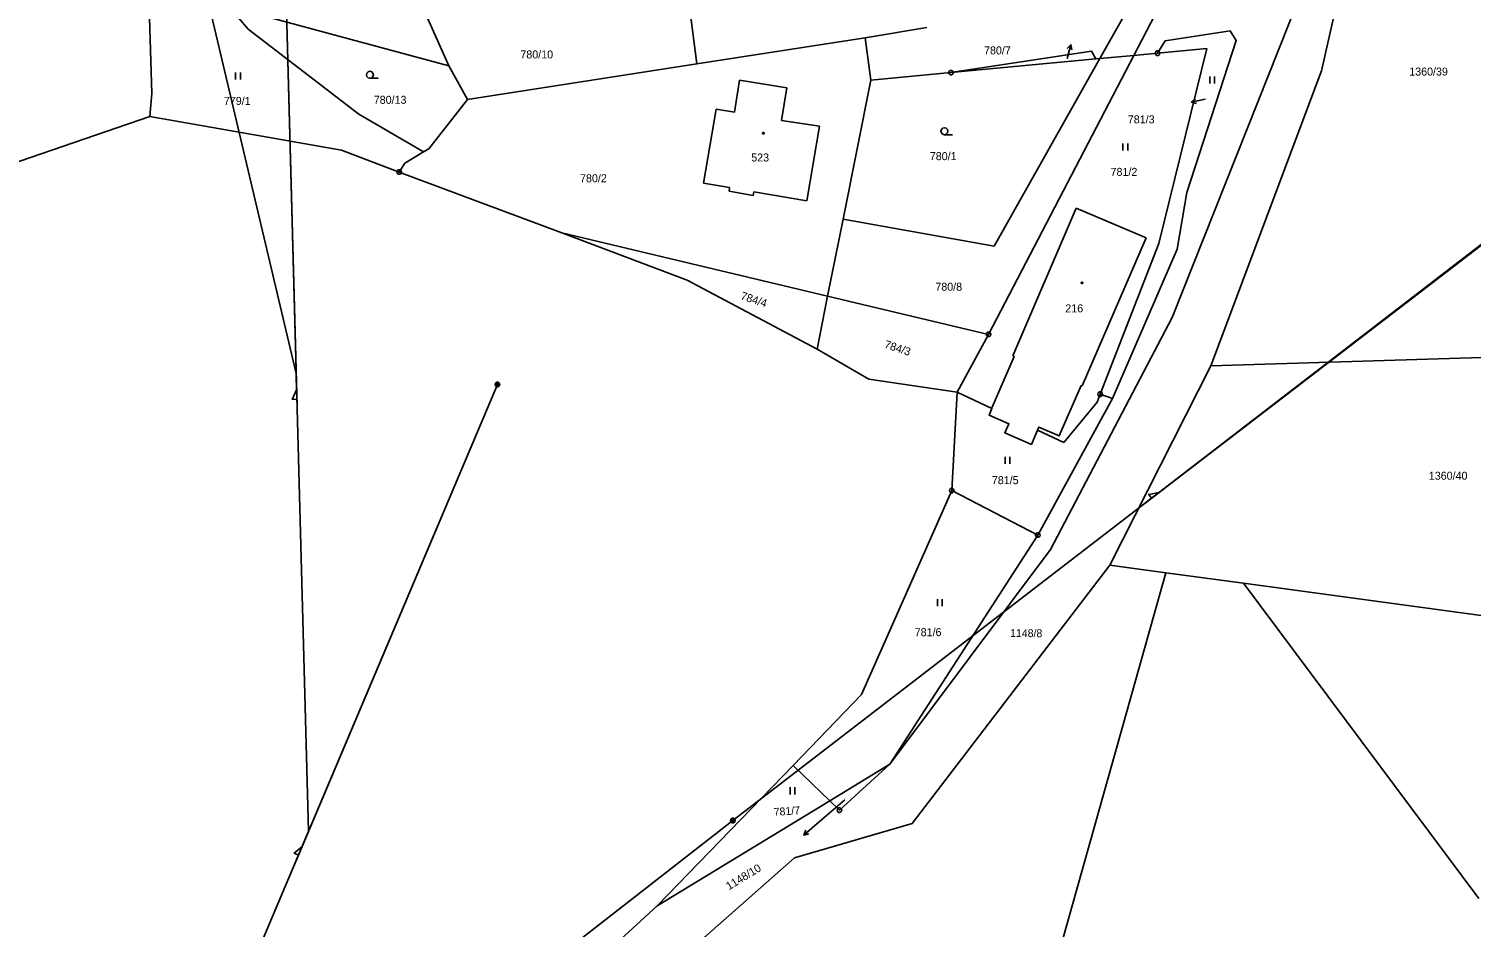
# Model space of a CAD drawing. Extents: x -747792 to -745414, y -1093712 to -1091463.
# Drawn here: x -746034.4 to -745881.2, y -1091741.3 to -1091645.8 of the extents above; entities that cross this region are included whole.
import ezdxf

# ---------------------------------------------------------------- set-up
doc = ezdxf.new("R2010")
doc.units = 0
for name, color, linetype in [('Pracovní_bod JDTM STC_VC', 7, 'Continuous'), ('Pracovní_bod JDTM STC_VC - výška', 7, 'Continuous'), ('Pracovní_bod JDTM STC_VC - číslo', 7, 'Continuous'), ('Pracovní_bod NN - výška', 7, 'Continuous'), ('Pracovní_bod polohopisu - výška', 7, 'Continuous'), ('Pracovní_bod polohopisu - číslo', 7, 'Continuous'), ('Pracovní_bod VN - výška', 7, 'Continuous')]:
    doc.layers.add(name, color=color, linetype=linetype)

msp = doc.modelspace()

# ---------------------------------------------------------------- linework, layer by layer
at = {"layer": 'Pracovní_bod JDTM STC_VC - výška'}
for points in [[(-745956.42, -1091656.79), (-745956.37, -1091656.8), (-745956.34, -1091656.85), (-745956.33, -1091656.88), (-745956.34, -1091656.92), (-745956.39, -1091656.96), (-745956.42, -1091656.96), (-745956.47, -1091656.95), (-745956.5, -1091656.92), (-745956.51, -1091656.88), (-745956.5, -1091656.83), (-745956.46, -1091656.8)], [(-745922.58, -1091672.69), (-745922.53, -1091672.7), (-745922.5, -1091672.74), (-745922.49, -1091672.77), (-745922.5, -1091672.81), (-745922.54, -1091672.85), (-745922.58, -1091672.85), (-745922.62, -1091672.84), (-745922.66, -1091672.81), (-745922.67, -1091672.77), (-745922.66, -1091672.73), (-745922.61, -1091672.69)]]:
    msp.add_lwpolyline(points, close=True, dxfattribs=at)
at = {"layer": 'Pracovní_bod JDTM STC_VC - číslo'}
for points in [[(-746012.47, -1091650.41), (-746012.47, -1091651.16)], [(-746011.97, -1091651.16), (-746011.97, -1091650.41)], [(-745998.21, -1091651.03), (-745998.4, -1091650.98), (-745998.53, -1091650.84), (-745998.58, -1091650.66), (-745998.53, -1091650.47), (-745998.4, -1091650.33), (-745998.21, -1091650.28), (-745998.02, -1091650.33), (-745997.89, -1091650.47), (-745997.83, -1091650.66), (-745997.89, -1091650.84), (-745998.02, -1091650.98), (-745998.21, -1091651.03), (-745997.33, -1091651.03)], [(-745908.99, -1091650.85), (-745908.99, -1091651.6)], [(-745908.49, -1091651.6), (-745908.49, -1091650.85)], [(-745937.19, -1091657.03), (-745937.38, -1091656.98), (-745937.51, -1091656.84), (-745937.57, -1091656.66), (-745937.51, -1091656.47), (-745937.38, -1091656.33), (-745937.19, -1091656.28), (-745937, -1091656.33), (-745936.86, -1091656.47), (-745936.82, -1091656.66), (-745936.86, -1091656.84), (-745937, -1091656.98), (-745937.19, -1091657.03), (-745936.32, -1091657.03)], [(-745918.22, -1091657.95), (-745918.22, -1091658.7)], [(-745917.72, -1091658.7), (-745917.72, -1091657.95)], [(-745930.74, -1091691.25), (-745930.74, -1091692)], [(-745930.24, -1091692), (-745930.24, -1091691.25)], [(-745937.94, -1091706.38), (-745937.94, -1091707.13)], [(-745937.44, -1091707.13), (-745937.44, -1091706.38)], [(-745953.57, -1091726.39), (-745953.57, -1091727.14)], [(-745953.07, -1091727.14), (-745953.07, -1091726.39)]]:
    msp.add_lwpolyline(points, dxfattribs=at)
at = {"layer": 'Pracovní_bod NN - výška'}
for points in [[(-745989.84, -1091649.69), (-745998.7, -1091629.75)], [(-745963.48, -1091649.5), (-745965.97, -1091630.16)], [(-745910.34, -1091635.63), (-745917.08, -1091648.59)], [(-745897.14, -1091650.23), (-745894.42, -1091638.17)], [(-746021.37, -1091652.64), (-746021.73, -1091641.08)], [(-745916.92, -1091642.28), (-745920.67, -1091648.93)], [(-745912.98, -1091676.47), (-745899.41, -1091642.18)], [(-746013.19, -1091643.39), (-745989.84, -1091649.69)], [(-746011.15, -1091645.82), (-746013.19, -1091643.39)], [(-746011.15, -1091645.82), (-745999.4, -1091654.83)], [(-745945.61, -1091646.72), (-745939.06, -1091645.64)], [(-745914.56, -1091648.35), (-745913.74, -1091647.04), (-745906.85, -1091645.98), (-745906.19, -1091647.02), (-745911.45, -1091663.16), (-745912.47, -1091669.18), (-745919.33, -1091685.08)], [(-745945.61, -1091646.72), (-745963.48, -1091649.5)], [(-745945.01, -1091651.24), (-745945.61, -1091646.72)], [(-745936.49, -1091650.43), (-745921.55, -1091648.14), (-745921.12, -1091648.97)], [(-745936.49, -1091650.43), (-745921.12, -1091648.97)], [(-745917.08, -1091648.59), (-745932.5, -1091678.25)], [(-745920.67, -1091648.93), (-745931.9, -1091668.86)], [(-745921.12, -1091648.97), (-745920.67, -1091648.93)], [(-745920.67, -1091648.93), (-745917.08, -1091648.59)], [(-745917.08, -1091648.59), (-745914.56, -1091648.35)], [(-745914.56, -1091648.35), (-745909.32, -1091647.86)], [(-745909.32, -1091647.86), (-745914.4, -1091668.59)], [(-745987.84, -1091653.29), (-745989.84, -1091649.69)], [(-745987.84, -1091653.29), (-745963.48, -1091649.5)], [(-745945.01, -1091651.24), (-745936.49, -1091650.43)], [(-745908.88, -1091681.58), (-745897.14, -1091650.23)], [(-745958.94, -1091651.23), (-745959.49, -1091654.63)], [(-745953.94, -1091652.04), (-745958.94, -1091651.23)], [(-745954.5, -1091655.51), (-745953.94, -1091652.04)], [(-745945.01, -1091651.24), (-745947.95, -1091666)], [(-746021.37, -1091652.64), (-746021.58, -1091655.08)], [(-745987.84, -1091653.29), (-745991.96, -1091658.52), (-745992.53, -1091658.86)], [(-746172.9, -1091707.09), (-746021.58, -1091655.08)], [(-746021.58, -1091655.08), (-746001.24, -1091658.68)], [(-745999.4, -1091654.83), (-745992.53, -1091658.86)], [(-745961.43, -1091654.32), (-745962.78, -1091662.18)], [(-745959.49, -1091654.63), (-745961.43, -1091654.32)], [(-745950.47, -1091656.11), (-745954.5, -1091655.51)], [(-745951.79, -1091664.05), (-745950.47, -1091656.11)], [(-746001.24, -1091658.68), (-745995.1, -1091660.99)], [(-745992.53, -1091658.86), (-745994.51, -1091660.06), (-745995.1, -1091660.99)], [(-745995.1, -1091660.99), (-745977.84, -1091667.47)], [(-745962.78, -1091662.18), (-745960, -1091662.65)], [(-745960, -1091662.65), (-745960.06, -1091663.03)], [(-745960.06, -1091663.03), (-745957.49, -1091663.47)], [(-745957.49, -1091663.47), (-745957.42, -1091663.09)], [(-745957.42, -1091663.09), (-745951.79, -1091664.05)], [(-745929.93, -1091680.54), (-745923.19, -1091664.83)], [(-745923.19, -1091664.83), (-745915.75, -1091667.99)], [(-745977.84, -1091667.47), (-745964.51, -1091672.48)], [(-745977.84, -1091667.47), (-745949.59, -1091674.19)], [(-745947.95, -1091666), (-745949.59, -1091674.19)], [(-745931.9, -1091668.86), (-745947.95, -1091666)], [(-745915.75, -1091667.99), (-745922.55, -1091683.71)], [(-745914.4, -1091668.59), (-745920.64, -1091684.61)], [(-745964.51, -1091672.48), (-745950.71, -1091679.81)], [(-745949.59, -1091674.19), (-745950.71, -1091679.81)], [(-745949.59, -1091674.19), (-745932.5, -1091678.25)], [(-745925.92, -1091701.12), (-745912.98, -1091676.47)], [(-745935.82, -1091684.4), (-745932.5, -1091678.25)], [(-745950.71, -1091679.81), (-745945.21, -1091683)], [(-745929.93, -1091680.54), (-745929.79, -1091680.61), (-745932.1, -1091685.98), (-745932.16, -1091686.13)], [(-745908.88, -1091681.58), (-745861.66, -1091680.15)], [(-745919.62, -1091702.79), (-745908.88, -1091681.58)], [(-745935.82, -1091684.4), (-745945.21, -1091683)], [(-745927.3, -1091688.43), (-745927.16, -1091688.11), (-745924.99, -1091689.04), (-745922.67, -1091683.67)], [(-745922.55, -1091683.71), (-745922.67, -1091683.67)], [(-745936.41, -1091694.84), (-745935.82, -1091684.4)], [(-745932.16, -1091686.13), (-745935.82, -1091684.4)], [(-745927.27, -1091699.58), (-745919.33, -1091685.08)], [(-745920.97, -1091685.46), (-745924.51, -1091689.75)], [(-745920.64, -1091684.61), (-745920.97, -1091685.46)], [(-745919.33, -1091685.08), (-745920.64, -1091684.61)], [(-745932.16, -1091686.13), (-745932.45, -1091686.82), (-745930.34, -1091687.75), (-745930.78, -1091688.71), (-745927.95, -1091689.94), (-745927.3, -1091688.43)], [(-745924.51, -1091689.75), (-745927.3, -1091688.43)], [(-745946.01, -1091716.54), (-745936.41, -1091694.84)], [(-745936.41, -1091694.84), (-745927.27, -1091699.58)], [(-745942.97, -1091723.95), (-745927.27, -1091699.58)], [(-745942.97, -1091723.95), (-745925.92, -1091701.12)], [(-745940.61, -1091730.24), (-745919.62, -1091702.79)], [(-745924.91, -1091743.52), (-745913.66, -1091703.59)], [(-745919.62, -1091702.79), (-745913.66, -1091703.59)], [(-745913.66, -1091703.59), (-745905.42, -1091704.71)], [(-745905.42, -1091704.71), (-745880.41, -1091738.2)], [(-745905.42, -1091704.71), (-745863.77, -1091710.37)], [(-745953.27, -1091724.06), (-745946.01, -1091716.54)], [(-745967.69, -1091739), (-745953.27, -1091724.06)], [(-745953.27, -1091724.06), (-745949.35, -1091727.84)], [(-745942.97, -1091723.95), (-745949.35, -1091727.84)], [(-745948.34, -1091728.82), (-745942.97, -1091723.95)], [(-745949.35, -1091727.84), (-745967.69, -1091739)], [(-745949.35, -1091727.84), (-745948.34, -1091728.82)], [(-745953.12, -1091733.88), (-745940.61, -1091730.24)], [(-746026.69, -1091798.86), (-745953.12, -1091733.88)], [(-746029.94, -1091796.18), (-745967.69, -1091739)]]:
    msp.add_lwpolyline(points, dxfattribs=at)
at = {"layer": 'Pracovní_bod polohopisu - výška'}
for points in [[(-745923.76, -1091647.46), (-745924.16, -1091648.91)], [(-745924.14, -1091647.88), (-745923.76, -1091647.46), (-745923.65, -1091648.01)], [(-745910.4, -1091653.72), (-745910.94, -1091653.58), (-745910.51, -1091653.23)], [(-745910.94, -1091653.58), (-745909.48, -1091653.26)], [(-745947.78, -1091727.73), (-745950.98, -1091730.49)], [(-745952.12, -1091731.47), (-745950.98, -1091730.49)], [(-745951.58, -1091731.33), (-745952.12, -1091731.47), (-745951.9, -1091730.95)]]:
    msp.add_lwpolyline(points, dxfattribs=at)
at = {"layer": 'Pracovní_bod polohopisu - číslo'}
for points in [[(-746006.03, -1091682.4), (-746025.71, -1091599.08), (-746015.47, -1091642.44)], [(-745913, -1091693.98), (-745803.42, -1091609.82), (-745859.6, -1091652.96)], [(-746004.72, -1091731.06), (-746007.25, -1091637.24), (-746005.94, -1091685.9)], [(-745959.66, -1091729.93), (-745869.11, -1091660.16), (-745915.77, -1091696.11)], [(-746005.95, -1091685.65), (-746005.96, -1091685.15), (-746006.46, -1091685.16), (-746005.99, -1091684.15), (-746006.03, -1091682.65)], [(-746026.14, -1091781.77), (-745984.67, -1091683.58), (-746006.09, -1091734.29)], [(-745984.75, -1091683.34), (-745984.59, -1091683.34), (-745984.47, -1091683.43), (-745984.42, -1091683.58), (-745984.47, -1091683.72), (-745984.59, -1091683.81), (-745984.75, -1091683.81), (-745984.87, -1091683.72), (-745984.92, -1091683.58), (-745984.87, -1091683.43), (-745984.75, -1091683.34), (-745984.73, -1091683.36), (-745984.61, -1091683.36), (-745984.53, -1091683.4), (-745984.81, -1091683.4), (-745984.85, -1091683.44), (-745984.49, -1091683.44), (-745984.49, -1091683.48), (-745984.85, -1091683.48), (-745984.87, -1091683.52), (-745984.47, -1091683.52), (-745984.45, -1091683.56), (-745984.89, -1091683.56), (-745984.89, -1091683.6), (-745984.45, -1091683.6), (-745984.47, -1091683.64), (-745984.87, -1091683.64), (-745984.86, -1091683.68), (-745984.46, -1091683.68), (-745984.49, -1091683.72), (-745984.84, -1091683.72), (-745984.81, -1091683.76), (-745984.53, -1091683.76), (-745984.58, -1091683.8), (-745984.75, -1091683.8)], [(-745915.57, -1091695.96), (-745915.18, -1091695.66), (-745915.48, -1091695.26), (-745914.39, -1091695.04), (-745913.2, -1091694.13)], [(-746095.38, -1091835.77), (-745959.66, -1091729.93), (-746028.9, -1091783.92)], [(-745959.74, -1091729.69), (-745959.58, -1091729.69), (-745959.46, -1091729.78), (-745959.41, -1091729.92), (-745959.46, -1091730.07), (-745959.58, -1091730.16), (-745959.74, -1091730.16), (-745959.86, -1091730.07), (-745959.91, -1091729.92), (-745959.86, -1091729.78), (-745959.74, -1091729.69), (-745959.72, -1091729.71), (-745959.6, -1091729.71), (-745959.52, -1091729.75), (-745959.8, -1091729.75), (-745959.84, -1091729.79), (-745959.48, -1091729.79), (-745959.48, -1091729.83), (-745959.84, -1091729.83), (-745959.86, -1091729.87), (-745959.46, -1091729.87), (-745959.44, -1091729.91), (-745959.88, -1091729.91), (-745959.88, -1091729.95), (-745959.44, -1091729.95), (-745959.46, -1091729.99), (-745959.86, -1091729.99), (-745959.85, -1091730.03), (-745959.45, -1091730.03), (-745959.48, -1091730.07), (-745959.83, -1091730.07), (-745959.8, -1091730.11), (-745959.52, -1091730.11), (-745959.57, -1091730.15), (-745959.74, -1091730.15)], [(-746005.99, -1091734.06), (-746005.79, -1091733.6), (-746006.25, -1091733.4), (-746005.41, -1091732.68), (-746004.82, -1091731.29)]]:
    msp.add_lwpolyline(points, dxfattribs=at)
at = {"layer": 'Pracovní_bod VN - výška'}
for points in [[(-745914.49, -1091648.11), (-745914.36, -1091648.21), (-745914.31, -1091648.35), (-745914.36, -1091648.5), (-745914.49, -1091648.59), (-745914.64, -1091648.59), (-745914.76, -1091648.5), (-745914.81, -1091648.35), (-745914.76, -1091648.21), (-745914.64, -1091648.11)], [(-745936.42, -1091650.19), (-745936.29, -1091650.28), (-745936.24, -1091650.43), (-745936.29, -1091650.57), (-745936.42, -1091650.67), (-745936.57, -1091650.67), (-745936.69, -1091650.57), (-745936.74, -1091650.43), (-745936.69, -1091650.28), (-745936.57, -1091650.19)], [(-745995.02, -1091660.75), (-745994.9, -1091660.84), (-745994.85, -1091660.99), (-745994.9, -1091661.14), (-745995.02, -1091661.23), (-745995.18, -1091661.23), (-745995.3, -1091661.14), (-745995.35, -1091660.99), (-745995.3, -1091660.84), (-745995.18, -1091660.75)], [(-745932.43, -1091678.01), (-745932.3, -1091678.1), (-745932.25, -1091678.25), (-745932.3, -1091678.4), (-745932.43, -1091678.49), (-745932.58, -1091678.49), (-745932.7, -1091678.4), (-745932.75, -1091678.25), (-745932.7, -1091678.1), (-745932.58, -1091678.01)], [(-745920.57, -1091684.37), (-745920.44, -1091684.47), (-745920.39, -1091684.61), (-745920.44, -1091684.76), (-745920.57, -1091684.85), (-745920.72, -1091684.85), (-745920.84, -1091684.76), (-745920.89, -1091684.61), (-745920.84, -1091684.47), (-745920.72, -1091684.37)], [(-745936.33, -1091694.6), (-745936.21, -1091694.7), (-745936.16, -1091694.84), (-745936.21, -1091694.99), (-745936.33, -1091695.08), (-745936.49, -1091695.08), (-745936.61, -1091694.99), (-745936.66, -1091694.84), (-745936.61, -1091694.7), (-745936.49, -1091694.6)], [(-745927.2, -1091699.34), (-745927.07, -1091699.44), (-745927.02, -1091699.58), (-745927.07, -1091699.73), (-745927.2, -1091699.82), (-745927.34, -1091699.82), (-745927.47, -1091699.73), (-745927.52, -1091699.58), (-745927.47, -1091699.44), (-745927.34, -1091699.34)], [(-745948.26, -1091728.58), (-745948.14, -1091728.68), (-745948.09, -1091728.82), (-745948.14, -1091728.97), (-745948.26, -1091729.06), (-745948.42, -1091729.06), (-745948.54, -1091728.97), (-745948.59, -1091728.82), (-745948.54, -1091728.68), (-745948.42, -1091728.58)]]:
    msp.add_lwpolyline(points, close=True, dxfattribs=at)
for points in [[(-745914.59, -1091648.35), (-745914.54, -1091648.35)], [(-745936.52, -1091650.43), (-745936.46, -1091650.43)], [(-745995.12, -1091660.99), (-745995.08, -1091660.99)], [(-745932.53, -1091678.25), (-745932.47, -1091678.25)], [(-745920.67, -1091684.61), (-745920.61, -1091684.61)], [(-745936.44, -1091694.84), (-745936.39, -1091694.84)], [(-745927.3, -1091699.58), (-745927.24, -1091699.58)], [(-745948.36, -1091728.82), (-745948.32, -1091728.82)]]:
    msp.add_lwpolyline(points, dxfattribs=at)

# ---------------------------------------------------------------- texts
at = {"layer": 'Pracovní_bod JDTM STC_VC'}
for s, height, p in [('780/10', 0.85, (-745982.23, -1091648.92)), ('780/7', 0.85, (-745932.98, -1091648.49)), ('780/14', 0.05, (-745924.23, -1091648.94)), ('1360/39', 0.85, (-745887.82, -1091650.74)), ('779/1', 0.85, (-746013.72, -1091653.86)), ('780/13', 0.85, (-745997.8, -1091653.74)), ('781/3', 0.05, (-745909.51, -1091653.26)), ('523', 0.85, (-745957.71, -1091659.87)), ('780/1', 0.85, (-745938.74, -1091659.73)), ('780/2', 0.85, (-745975.89, -1091662.08)), ('781/2', 0.85, (-745919.54, -1091661.4)), ('780/8', 0.85, (-745938.15, -1091673.61)), ('216', 0.85, (-745924.35, -1091675.91)), ('781/5', 0.85, (-745932.15, -1091694.17)), ('1360/40', 0.85, (-745885.74, -1091693.7)), ('781/6', 0.85, (-745940.34, -1091710.33))]:
    msp.add_text(s, height=height, dxfattribs=at).set_placement(p)
for s, height, rotation, p in [('784/4', 0.85, 341.8839, (-745958.9, -1091674.5)), ('784/3', 0.85, 341.8839, (-745943.64, -1091679.66)), ('1148/8', 0.835, 359.4737, (-745930.21, -1091710.41)), ('781/7', 0.835, 3.9534, (-745955.29, -1091729.44)), ('1148/10', 0.05, 36.612, (-745947.85, -1091727.63))]:
    msp.add_text(s, height=height, rotation=rotation, dxfattribs=at).set_placement(p)
at = {"layer": 'Pracovní_bod polohopisu - výška'}
msp.add_text('781/3', height=0.85, dxfattribs=at).set_placement((-745917.71, -1091655.82))
msp.add_text('1148/10', height=0.85, rotation=31.4554, dxfattribs=at).set_placement((-745960.07, -1091737.35))

doc.saveas('drawing.dxf')
